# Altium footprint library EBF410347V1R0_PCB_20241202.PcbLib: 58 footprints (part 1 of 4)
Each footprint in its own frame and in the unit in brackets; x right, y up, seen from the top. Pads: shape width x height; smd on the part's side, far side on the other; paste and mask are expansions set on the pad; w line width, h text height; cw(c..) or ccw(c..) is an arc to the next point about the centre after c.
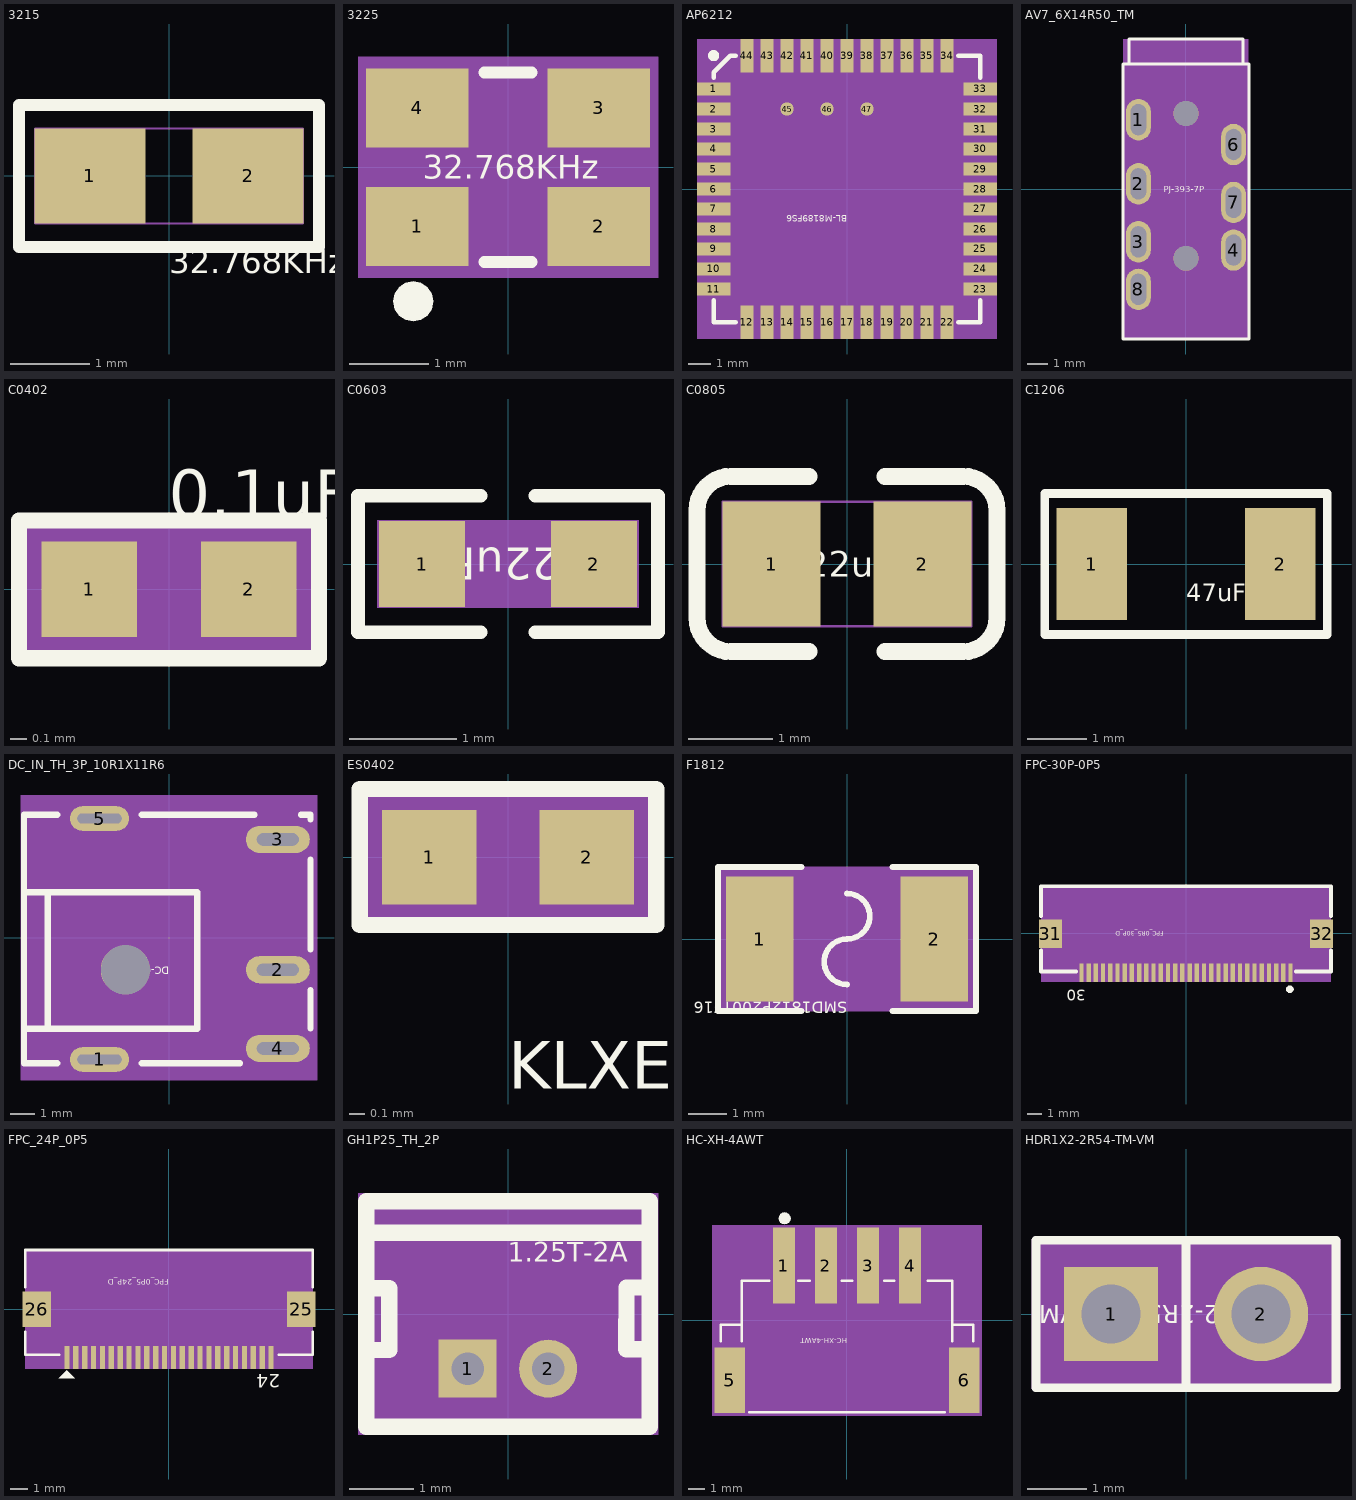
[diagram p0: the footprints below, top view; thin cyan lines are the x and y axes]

## 3215 [mm] "3215"
pads (2):
  rect 1.4x1.2 smd: 1(-1.001,0) 2(1.001,0)
Top Overlay:
  lines w0.15: -1.9,-0.899 -1.9,0.899 1.9,0.899 1.9,-0.899 -1.9,-0.899
  text "32.768KHz" at 0,-1.23 h0.3
Top 3D Body:
  lines w0.025: -1.699,-0.599 -1.699,0.599 1.699,0.599 1.699,-0.599 -1.699,-0.599
Mechanical 14:
  text "1" at -1.001,-0.163 h0.41
  text "2" at 1.001,-0.163 h0.41

## 3225 [mm] "3225"
pads (4):
  rect 1.3x1 smd: 1(-1.15,-0.75) 2(1.15,-0.75) 3(1.15,0.75) 4(-1.15,0.75)
Top Overlay:
  dashed: -0.945,-1.7 -0.965,-1.602 -1.02,-1.52 -1.102,-1.465 -1.2,-1.445 -1.298,-1.465 -1.325,-1.483 -1.38,-1.52 -1.435,-1.602 -1.455,-1.7 -1.435,-1.798 -1.38,-1.88 -1.325,-1.917 -1.298,-1.935 -1.2,-1.955 -1.102,-1.935 -1.02,-1.88 -0.965,-1.798
  lines w0.15: -0.3,-1.2 0.3,-1.2 ; -0.3,1.2 0.3,1.2
  text "32.768KHz" at -1.08,-0.15 h0.3
Top 3D Body:
  region: -1.9,1.4 -1.9,-1.4 1.9,-1.4 1.9,1.4
Mechanical 14:
  text "2" at 0.85,-0.75 h0.75
  text "3" at 0.85,0.75 h0.75
  text "4" at -1.45,0.75 h0.75
  text "1" at -1.45,-0.75 h0.75
Top Assembly:
  lines w0.15: -1.6,-1.25 1.6,-1.25 1.6,1.25 -1.6,1.25 -1.6,-1.25
3D body: height 3.81, standoff 0, extent -1.9,-1.4 1.9,1.4

## AP6212 [mm] "AP6212"
pads (47):
  rect 1.5x0.6 smd: 1(-6,4.5) 2(-6,3.6) 3(-6,2.7) 4(-6,1.8) 5(-6,0.9) 6(-6,0) 7(-6,-0.9) 8(-6,-1.8) 9(-6,-2.7) 10(-6,-3.6) 11(-6,-4.5) 23(6,-4.5) 24(6,-3.6) 25(6,-2.7) 26(6,-1.8) 27(6,-0.9) 28(6,0) 29(6,0.9) 30(6,1.8) 31(6,2.7) 32(6,3.6) 33(6,4.5)
  rect 0.6x1.5 smd: 12(-4.5,-6) 13(-3.6,-6) 14(-2.7,-6) 15(-1.8,-6) 16(-0.9,-6) 17(0,-6) 18(0.9,-6) 19(1.8,-6) 20(2.7,-6) 21(3.6,-6) 22(4.5,-6) 34(4.5,6) 35(3.6,6) 36(2.7,6) 37(1.8,6) 38(0.9,6) 39(0,6) 40(-0.9,6) 41(-1.8,6) 42(-2.7,6) 43(-3.6,6) 44(-4.5,6)
  round 0.6 smd: 45(-2.7,3.6) 46(-0.9,3.6) 47(0.9,3.6)
Top Overlay:
  circle w0.25: c-6,6 r0.125
  lines w0.2: -6,-5 -6,-6 -5,-6 ; -6,5 -6,5.25 -5.25,6 -5,6 ; 5,-6 6,-6 6,-5 ; 5,6 6,6 6,5
  text "BL-M8189FS6" at 0,-1.17 h0.3
Top 3D Body:
  region: -6.75,-6.75 6.75,-6.75 6.75,6.75 -6.75,6.75
Mechanical 14:
  text "31" at 6,1.989 h0.89
  text "33" at 6,3.789 h0.89
  text "1" at -6,4.144 h0.89
  text "3" at -6,2.344 h0.89
  text "36" at 2.7,5.289 h0.89
  text "20" at 2.7,-6.711 h0.89
  text "19" at 1.8,-6.711 h0.89
  text "15" at -1.8,-6.711 h0.89
  text "16" at -0.9,-6.711 h0.89
  text "14" at -2.7,-6.711 h0.89
  text "18" at 0.9,-6.711 h0.89
  text "17" at 0,-6.711 h0.89
  text "42" at -2.7,5.289 h0.89
  text "2" at -6,3.244 h0.89
  text "43" at -3.6,5.289 h0.89
  text "28" at 6,-0.711 h0.89
  text "7" at -6,-1.255 h0.89
  text "44" at -4.5,5.289 h0.89
  text "12" at -4.5,-6.711 h0.89
  text "13" at -3.6,-6.711 h0.89
  text "34" at 4.5,5.289 h0.89
  text "6" at -6,-0.356 h0.89
  text "27" at 6,-1.611 h0.89
  text "41" at -1.8,5.289 h0.89
  text "22" at 4.5,-6.711 h0.89
  text "9" at -6,-3.056 h0.89
  text "26" at 6,-2.511 h0.89
  text "24" at 6,-4.311 h0.89
  text "25" at 6,-3.411 h0.89
  text "11" at -6,-5.211 h0.89
  text "10" at -6,-4.311 h0.89
  text "29" at 6,0.189 h0.89
  text "21" at 3.6,-6.711 h0.89
  text "23" at 6,-5.211 h0.89
  text "30" at 6,1.089 h0.89
  text "8" at -6,-2.156 h0.89
  text "5" at -6,0.544 h0.89
  text "47" at 0.9,2.889 h0.89
  text "46" at -0.9,2.889 h0.89
  text "45" at -2.7,2.889 h0.89
  text "40" at -0.9,5.289 h0.89
  text "4" at -6,1.444 h0.89
  text "39" at 0,5.289 h0.89
  text "38" at 0.9,5.289 h0.89
  text "37" at 1.8,5.289 h0.89
  text "35" at 3.6,5.289 h0.89
  text "32" at 6,2.889 h0.89
3D body: height 3.81, standoff 0, extent -6.75,-6.75 6.75,6.75

## AV7_6X14R50_TM [mm] "AV7_6X14R50_TM"
pads (9):
  oval 1.2x2 hole 1.5 slot 0.75 at 0 deg: 1(-2.3,3.35) 2(-2.3,0.25) 3(-2.3,-2.55) 4(2.3,-2.95) 6(2.3,2.15) 7(2.3,-0.65) 8(-2.3,-4.85)
  round 1.2 hole 1.2 unplated: ""(0,-3.35) ""(0,3.65)
Top Overlay:
  lines w0.15: -2.75,6.05 -2.75,7.25 2.75,7.25 2.75,6.05 ; -3.05,-7.25 -3.05,6.05 3.05,6.05 3.05,-7.25 -3.05,-7.25
  text "PJ-393-7P" at -1.08,-0.15 h0.3
Top 3D Body:
  region: -3,-7.25 -3,7.25 3,7.25 3,-7.25
Mechanical 14:
  text "2" at -2.574,0.13 h0.64
  text "6" at 2.026,2.03 h0.64
  text "3" at -2.574,-2.67 h0.64
  text "4" at 2.026,-3.07 h0.64
  text "1" at -2.574,3.23 h0.64
  text "8" at -2.574,-4.97 h0.64
  text "7" at 2.026,-0.77 h0.64
Top Assembly:
  lines w0.025: -3,-7.25 -3,7.25 3,7.25 3,-7.25 -3,-7.25
3D body: height 3.81, standoff 0, extent -3,-7.25 3,7.25

## C0402 [mm] "C0402"
pads (2):
  rect 0.599x0.599 smd: 1(-0.5,0) 2(0.5,0)
Top Overlay:
  lines w0.102: -0.94,-0.432 0.94,-0.432 0.94,0.432 -0.94,0.432 -0.94,-0.432
  text "0.1uF" at 0,0.45 h0.3
Top 3D Body:
  region: 0.94,0.432 0.94,-0.432 -0.94,-0.432 -0.94,0.432
Mechanical 14:
  text "2" at 0.5,0.457 h1.14
  text "1" at -0.5,0.457 h1.14
Top Assembly:
  dashed: -0.94,-0.432 -0.94,0.432 0.94,0.432 0.94,-0.432
3D body: height 3.81, standoff 0, extent -0.94,-0.432 0.94,0.432

## C0603 [mil] "C0603"
pads (2):
  rect 31.5x31.5 smd: 1(-31.5,0) 2(31.5,0)
Top Overlay:
  lines w5: -10,-25 -55,-25 -55,25 -10,25 ; 10,-25 55,-25 55,25 10,25
  text "22uF" at 18.9,5.91 h11.81
Top 3D Body:
  region: -48,16 48,16 48,-16 -48,-16
Mechanical 14:
  text "2" at 45.5,0 h35
  text "1" at -17.5,0 h35
Top Assembly:
  text "C0603" at -117,37 h11.81
3D body: height 150, standoff 0, extent -48,-16 48,16

## C0805 [mm] "C0805"
pads (2):
  rect 1.16x1.47 smd: 1(-0.89,0) 2(0.89,0)
Top Overlay:
  lines w0.2: -0.45,-1.035 -1.37,-1.035 cw(c-1.37,-0.635) -1.77,-0.635 -1.77,0.635 cw(c-1.37,0.635) -1.37,1.035 -0.45,1.035 ; 0.45,-1.035 1.37,-1.035 ccw(c1.37,-0.635) 1.77,-0.635 1.77,0.635 ccw(c1.37,0.635) 1.37,1.035 0.45,1.035
  text "22uF" at -0.48,-0.15 h0.3
Top 3D Body:
  lines w0.025: -1.47,-0.735 1.47,-0.735 1.47,0.735 -1.47,0.735 -1.47,-0.735
Mechanical 14:
  text "2" at 0.585,0 h0.76
  text "1" at -1.195,0 h0.76

## C1206 [mm] "C1206"
pads (2):
  rect 1.2x1.9 smd: 1(-1.6,0) 2(1.6,0)
Top Overlay:
  lines w0.15: -2.4,-1.2 -2.4,1.2 2.4,1.2 2.4,-1.2 0.6,-1.2 -2.4,-1.2
  text "47uF" at 0,-0.63 h0.3
Top 3D Body:
  lines w0.025: -2.4,-1.2 -2.4,1.2 2.4,1.2 2.4,-1.2 -2.4,-1.2
Mechanical 14:
  text "2" at 1.6,-0.356 h0.89
  text "1" at -1.6,-0.356 h0.89
Top Assembly:
  lines w0.025: -2.4,-1.2 -2.4,1.2 2.4,1.2 2.4,-1.2 -2.4,-1.2

## DC_IN_TH_3P_10R1X11R6 [mil] "DC_IN_TH_3P_10R1X11R6"
pads (6):
  oval 94.5x39.4 hole 70.9 slot 15.7 at 90 deg: 1(-111.25,-194.9) 5(-111.25,190.9)
  oval 102.4x43.3 hole 66.9 slot 19.7 at 90 deg: 2(174.25,-51.2) 3(174.25,157.4) 4(174.25,-177.2)
  round 78.7 hole 78.7 unplated: ""(-69.85,-51.2)
Top Overlay:
  lines w10: -232.25,-145.7 45.25,-145.7 45.25,72.8 -222.45,72.8 -232.25,72.8 ; -193.95,-145.7 -193.95,72.8 ; -178.95,-200.8 -232.25,-200.8 -232.25,196.8 -178.95,196.8 ; -43.45,-200.8 113.65,-200.8 ; -43.45,196.8 136.95,196.8 ; 211.45,196.8 226.35,196.8 226.35,189.7 ; 226.35,-145 226.35,-83.5 ; 226.35,-19 226.35,125.2
  text "DC-044A-20A" at 0.01,-46.06 h11.81
Top 3D Body:
  region: -237.25,-228.4 237.25,-228.4 237.25,228.4 -237.25,228.4
Mechanical 14:
  text "2" at 174.25,-55.14 h9.84
  text "3" at 174.25,153.47 h9.84
  text "4" at 174.25,-181.14 h9.84
  text "5" at -111.25,186.97 h9.84
  text "1" at -111.25,-198.84 h9.84
Mechanical 17:
  dashed: -232.25,-141.8 41.35,-141.8 41.35,68.9 -232.25,68.9 -232.25,78.7 51.15,78.7 51.15,-151.6 -232.25,-151.6
3D body: height 150, standoff 0, extent -237.25,-228.4 237.25,228.4

## ES0402 [mm] "ES0402"
pads (2):
  rect 0.599x0.599 smd: 1(-0.5,0) 2(0.5,0)
Top Overlay:
  lines w0.102: -0.94,-0.432 0.94,-0.432 0.94,0.432 -0.94,0.432 -0.94,-0.432
  text "KLXES15AAA1" at 0,-1.47 h0.3
Top 3D Body:
  region: 0.94,0.432 0.94,-0.432 -0.94,-0.432 -0.94,0.432
Mechanical 14:
  text "2" at 0.5,-0.457 h1.14
  text "1" at -0.5,-0.457 h1.14
Top Assembly:
  dashed: -0.94,-0.432 -0.94,0.432 0.94,0.432 0.94,-0.432
3D body: height 3.81, standoff 0, extent -0.94,-0.432 0.94,0.432

## F1812 [mm] "F1812"
pads (2):
  rect 1.78x3.3 smd: 1(-2.305,0) 2(2.305,0)
Top Overlay:
  lines w0.15: -1.2,-1.9 -3.4,-1.9 -3.4,1.9 -1.2,1.9 ; 0,-1.2 cw(c0,-0.6) 0,0 ccw(c0,0.6) 0,1.2 ; 1.2,-1.9 3.4,-1.9 3.4,1.9 1.2,1.9
  text "SMD1812P200TF16" at 0,-1.65 h0.3
Top 3D Body:
  region: -3.4,-1.9 3.4,-1.9 3.4,1.9 -3.4,1.9
Mechanical 14:
  text "1" at -2.305,-0.305 h0.76
  text "2" at 2.305,-0.305 h0.76
3D body: height 3.81, standoff 0, extent -3.4,-1.9 3.4,1.9

## FPC-30P-0P5 [mm] "FPC-30P-0P5"
pads (32):
  rect 0.3x1.3 smd: 1(7.25,-2.733) 2(6.75,-2.733) 3(6.25,-2.733) 4(5.75,-2.733) 5(5.25,-2.733) 6(4.75,-2.733) 7(4.25,-2.733) 8(3.75,-2.733) 9(3.25,-2.733) 10(2.75,-2.733) 11(2.25,-2.733) 12(1.75,-2.733) 13(1.25,-2.733) 14(0.75,-2.733) 15(0.25,-2.733) 16(-0.25,-2.733) 17(-0.75,-2.733) 18(-1.25,-2.733) 19(-1.75,-2.733) 20(-2.25,-2.733) 21(-2.75,-2.733) 22(-3.25,-2.733) 23(-3.75,-2.733) 24(-4.25,-2.733) 25(-4.75,-2.733) 26(-5.25,-2.733) 27(-5.75,-2.733) 28(-6.25,-2.733) 29(-6.75,-2.733) 30(-7.25,-2.733)
  rect 1.6x2 smd: 31(-9.4,-0.032) 32(9.4,-0.032)
Top Overlay:
  dashed: 7.455,-3.882 7.435,-3.98 7.38,-4.063 7.297,-4.118 7.2,-4.137 7.102,-4.118 7.075,-4.099 7.02,-4.063 6.964,-3.98 6.945,-3.882 6.964,-3.785 7.02,-3.702 7.075,-3.666 7.102,-3.647 7.2,-3.628 7.297,-3.647 7.38,-3.702 7.435,-3.785
  lines w0.254: -10.05,-1.164 -10.05,-2.652 -7.631,-2.652 ; -10.05,1.199 -10.05,3.268 10.04,3.268 10.05,3.257 ; 7.631,-2.652 10.05,-2.652 10.05,-1.164 ; 10.05,1.199 10.05,3.257 ; 10.05,3.257 10.05,3.257
  text "FPC_0R5_30P_D" at -1.56,0.15 h0.3
  text "30" at -6.934,-3.903 h0.76
Top 3D Body:
  region: -10.052,3.35 -10.052,-3.35 10.052,-3.35 10.052,3.35
Mechanical 14:
  text "6" at 4.546,-2.733 h0.25
  text "8" at 3.546,-2.733 h0.25
  text "31" at -8.89,-0.112 h0.25
  text "28" at -6.657,-2.733 h0.25
  text "25" at -5.157,-2.733 h0.25
  text "22" at -3.657,-2.733 h0.25
  text "19" at -2.157,-2.733 h0.25
  text "16" at -0.657,-2.733 h0.25
  text "7" at 4.047,-2.733 h0.25
  text "32" at 10.16,-0.112 h0.25
  text "10" at 2.343,-2.733 h0.25
  text "9" at 3.047,-2.733 h0.25
  text "15" at -0.157,-2.733 h0.25
  text "12" at 1.343,-2.733 h0.25
  text "13" at 0.843,-2.733 h0.25
  text "11" at 1.843,-2.733 h0.25
  text "24" at -4.657,-2.733 h0.25
  text "23" at -4.157,-2.733 h0.25
  text "30" at -7.657,-2.733 h0.25
  text "29" at -7.157,-2.733 h0.25
  text "18" at -1.657,-2.733 h0.25
  text "17" at -1.157,-2.733 h0.25
  text "21" at -3.157,-2.733 h0.25
  text "20" at -2.657,-2.733 h0.25
  text "27" at -6.157,-2.733 h0.25
  text "26" at -5.657,-2.733 h0.25
  text "5" at 5.047,-2.733 h0.25
  text "4" at 5.546,-2.733 h0.25
  text "3" at 6.047,-2.733 h0.25
  text "2" at 6.546,-2.733 h0.25
  text "1" at 7.047,-2.733 h0.25
  text "14" at 0.343,-2.733 h0.25
3D body: height 3.81, standoff 0, extent -10.052,-3.35 10.052,3.35

## FPC_24P_0P5 [mm] "FPC_24P_0P5"
pads (26):
  rect 0.3x1.3 smd: 1(-5.75,-2.701) 2(-5.25,-2.701) 3(-4.75,-2.701) 4(-4.25,-2.701) 5(-3.75,-2.701) 6(-3.25,-2.701) 7(-2.75,-2.701) 8(-2.25,-2.701) 9(-1.75,-2.701) 10(-1.25,-2.701) 11(-0.75,-2.701) 12(-0.25,-2.701) 13(0.25,-2.701) 14(0.75,-2.701) 15(1.25,-2.701) 16(1.75,-2.701) 17(2.25,-2.701) 18(2.75,-2.701) 19(3.25,-2.701) 20(3.75,-2.701) 21(4.25,-2.701) 22(4.75,-2.701) 23(5.25,-2.701) 24(5.75,-2.701)
  rect 1.6x2 smd: 25(7.45,0.001) 26(-7.45,0.001)
Top Overlay:
  dashed: -6.2,-3.868 -5.302,-3.868 -5.751,-3.419
  lines w0.15: -8.1,-1.25 -8.1,-2.55 -6.2,-2.55 ; -8.1,1.25 -8.1,3.35 8.1,3.35 8.1,1.25 ; 6.2,-2.55 8.1,-2.55 8.1,-1.25
  text "FPC_0P5_24P_D" at 0,1.71 h0.3
  text "24" at 6.263,-3.643 h0.76
Top 3D Body:
  region: -8.1,-3.35 -8.1,3.35 8.1,3.35 8.1,-3.35
Mechanical 14:
  text "4" at -4.25,-2.447 h0.64
  text "23" at 5.25,-2.193 h0.64
  text "24" at 5.75,-2.193 h0.64
  text "25" at 7.45,0.509 h0.64
  text "26" at -7.45,0.509 h0.64
  text "11" at -0.75,-2.193 h0.64
  text "6" at -3.25,-2.447 h0.64
  text "9" at -1.75,-2.447 h0.64
  text "7" at -2.75,-2.447 h0.64
  text "10" at -1.25,-2.193 h0.64
  text "5" at -3.75,-2.447 h0.64
  text "12" at -0.25,-2.193 h0.64
  text "8" at -2.25,-2.447 h0.64
  text "15" at 1.25,-2.193 h0.64
  text "3" at -4.75,-2.447 h0.64
  text "2" at -5.25,-2.447 h0.64
  text "1" at -5.75,-2.447 h0.64
  text "22" at 4.75,-2.193 h0.64
  text "21" at 4.25,-2.193 h0.64
  text "20" at 3.75,-2.193 h0.64
  text "19" at 3.25,-2.193 h0.64
  text "18" at 2.75,-2.193 h0.64
  text "17" at 2.25,-2.193 h0.64
  text "16" at 1.75,-2.193 h0.64
  text "14" at 0.75,-2.193 h0.64
  text "13" at 0.25,-2.193 h0.64
3D body: height 3.81, standoff 0, extent -8.1,-3.35 8.1,3.35

## GH1P25_TH_2P [mm] "GH1P25_TH_2P"
pads (2):
  rect 0.9x0.9 hole 0.5: 1(-0.626,-0.849)
  round 0.9 hole 0.5: 2(0.624,-0.849)
Top Overlay:
  lines w0.254: -2.202,0.401 -1.841,0.401 -1.841,-0.559 -2.161,-0.559 ; -2.201,1.262 2.199,1.262 ; 2.159,-0.549 1.839,-0.548 1.839,0.411 2.2,0.411 ; 2.199,-1.749 -2.201,-1.749 -2.201,1.751 2.199,1.751 ; 2.202,-1.751 2.202,1.749
  text "1.25T-2A" at 0,0.81 h0.3
Bottom Overlay:
  lines w0.2: -0.001,-1.549 -0.001,-0.149
  lines w0.3: -1.401,-1.549 -1.401,-0.149 1.399,-0.149 1.399,-1.549 -1.101,-1.549 -1.401,-1.549
Top 3D Body:
  region: -2.329,-1.878 2.329,-1.878 2.329,1.878 -2.329,1.878
Mechanical 14:
  text "2" at 0.624,-0.749 h0.25
  text "1" at -0.626,-0.749 h0.25
3D body: height 3.81, standoff 0, extent -2.329,-1.878 2.329,1.878

## HC-XH-4AWT [mm] "HC-XH-4AWT"
pads (6):
  rect 1.3x4.5 smd: 1(-3.75,3.25) 2(-1.25,3.25) 3(1.25,3.25) 4(3.75,3.25)
  rect 1.8x3.9 smd: 5(-6.95,-3.55) 6(6.95,-3.55)
Top Overlay:
  dashed: -3.7,6.407 -3.837,6.38 -3.952,6.302 -4.03,6.187 -4.057,6.05 -4.03,5.913 -4.004,5.875 -3.952,5.798 -3.837,5.72 -3.7,5.693 -3.563,5.72 -3.448,5.798 -3.396,5.875 -3.37,5.913 -3.343,6.05 -3.37,6.187 -3.448,6.302 -3.563,6.38
  lines w0.15: -7.5,-1.25 -7.5,-0.25 -6.3,-0.25 ; -6.25,-1.25 -6.25,2.35 -4.6,2.35 ; -5.8,-5.45 5.8,-5.45 ; -2.9,2.35 -2.2,2.35 ; -0.3,2.35 0.3,2.35 ; 2.2,2.35 2.8,2.35 ; 4.8,2.35 6.25,2.35 6.25,-1.25 ; 6.3,-0.25 7.5,-0.25 7.5,-1.25
  text "HC-XH-4AWT" at 0,-1.05 h0.3
Top 3D Body:
  region: -8,5.65 -8,-5.65 8,-5.65 8,5.65
Mechanical 14:
  text "6" at 6.95,-3.804 h0.64
  text "5" at -6.95,-3.804 h0.64
  text "2" at -1.25,2.996 h0.64
  text "1" at -3.75,2.996 h0.64
  text "4" at 3.75,2.996 h0.64
  text "3" at 1.25,2.996 h0.64
Top Assembly:
  lines w0.15: -6.25,-5.45 6.25,-5.45 6.25,2.35 -6.25,2.35 -6.25,-5.45
3D body: height 3.81, standoff 0, extent -8,-5.65 8,5.65

## HDR1X2-2R54-TM-VM [mm] "HDR1X2-2R54-TM-VM"
pads (2):
  rect 1.6x1.6 hole 1: 1(-1.27,0)
  round 1.6 hole 1: 2(1.27,0)
Top Overlay:
  lines w0.15: 0,-1.25 0,1.25 ; -2.54,-1.25 2.54,-1.25 2.54,1.25 -2.54,1.25 -2.54,-1.25
  text "HDR1X2-2R54-TM-VM" at 2.04,0.15 h0.3
Bottom Overlay:
  lines w0.5: 0,-0.55 0,0.55
Top 3D Body:
  region: -2.54,1.25 -2.54,-1.25 2.54,-1.25 2.54,1.25
Mechanical 14:
  text "1" at -1.016,0 h0.64
  text "2" at 1.524,0 h0.64
Top Assembly:
  lines w0.15: -2.54,-1.25 2.54,-1.25 2.54,1.25 -2.54,1.25 -2.54,-1.25
3D body: height 3.81, standoff 0, extent -2.54,-1.25 2.54,1.25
